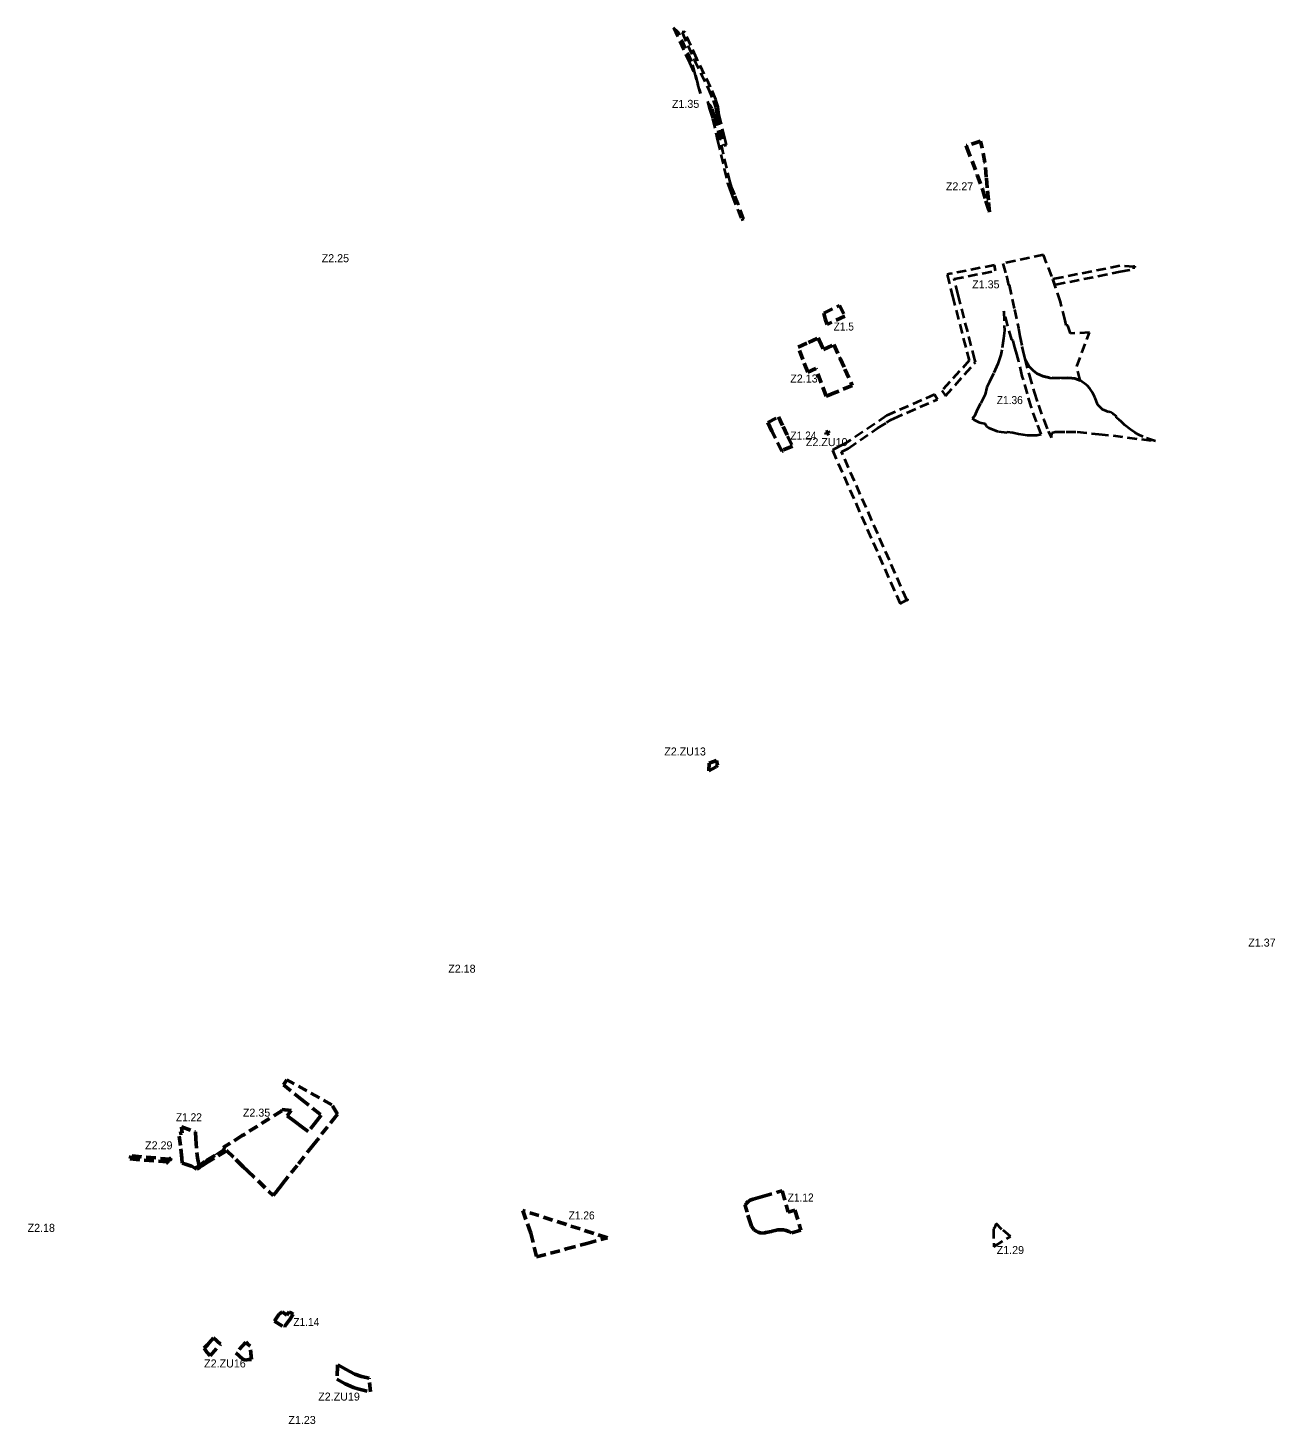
# Model space of a CAD drawing. Extents: x -650368 to -643203, y -1074215 to -1066658.
# Drawn here: x -650368 to -647095, y -1070321 to -1066658 of the extents above; entities that cross this region are included whole.
import ezdxf
from ezdxf.enums import TextEntityAlignment as Align

# ---------------------------------------------------------------- set-up
doc = ezdxf.new("R2010")
doc.units = 0
doc.header["$LTSCALE"] = 8.4
doc.header["$PDMODE"] = 32
doc.header["$PDSIZE"] = 4.2
doc.linetypes.add('MEDIUM_DASHED', pattern=[4.5, 3, -1.5])
for name, color, linetype, lineweight in [('1', 7, 'Continuous', 13), ('57', 7, 'MEDIUM_DASHED', 40), ('58', 7, 'MEDIUM_DASHED', 53)]:
    doc.layers.add(name, color=color, linetype=linetype, lineweight=lineweight)
for name, color, linetype in [('60', 7, 'Continuous'), ('61', 7, 'Continuous'), ('62', 7, 'Continuous')]:
    doc.layers.add(name, color=color, linetype=linetype)

msp = doc.modelspace()

# ---------------------------------------------------------------- linework, layer by layer
at = {"layer": '1'}
msp.add_line((-649849.496, -1069598.673), (-649903.756, -1069631.653), dxfattribs=at)
at = {"layer": '57'}
for p, q in [((-648495.63, -1067161.363), (-648489.1, -1067158.84)), ((-647408.2, -1067742.37), (-647440.81, -1067731.38))]:
    msp.add_line(p, q, dxfattribs=at)
for points in [[(-648602.97, -1066830.11), (-648616.86, -1066779.79), (-648625.44, -1066746.45), (-648659.95, -1066670.89), (-648662.46, -1066668.53), (-648673.407, -1066658.275), (-648631.791, -1066749.394)], [(-648576.145, -1066813.802), (-648612.763, -1066739.165), (-648643.925, -1066668.483), (-648651.042, -1066669.551), (-648651.1, -1066669.56)], [(-648651.1, -1066669.56), (-648619.11, -1066742.12), (-648582.52, -1066816.7)], [(-648631.791, -1066749.394), (-648616.104, -1066782.727), (-648602.97, -1066830.11)], [(-648582.52, -1066816.7), (-648569.13, -1066848.61), (-648566.63, -1066856.72), (-648563.48, -1066866.96), (-648560.2, -1066888.58), (-648541.521, -1066966.657), (-648534.701, -1066965.077), (-648538.812, -1066947.891)], [(-648538.812, -1066947.891), (-648553.323, -1066887.238), (-648556.637, -1066865.397), (-648559.94, -1066854.66), (-648562.542, -1066846.219), (-648576.145, -1066813.802)], [(-648571.96, -1066869.37), (-648577.99, -1066860.17), (-648583.94, -1066851.11), (-648578.702, -1066871.259)], [(-648578.702, -1066871.259), (-648571.167, -1066896.326), (-648557.816, -1066953.444)], [(-648489.1, -1067158.84), (-648512.95, -1067095.97), (-648520.4, -1067077.42), (-648524.93, -1067063.35), (-648533.66, -1067026), (-648551, -1066951.85), (-648564.4, -1066894.52), (-648571.96, -1066869.37)], [(-648557.816, -1066953.444), (-648540.476, -1067027.594), (-648531.681, -1067065.222)], [(-648531.681, -1067065.222), (-648526.988, -1067079.8), (-648519.471, -1067098.516), (-648495.644, -1067161.326)], [(-647638.68, -1067439.06), (-647642.686, -1067438.46), (-647645.78, -1067425.81), (-647658.13, -1067376.99), (-647680.64, -1067310.37), (-647702.42, -1067253.98), (-647809.02, -1067276.271)], [(-647809.02, -1067276.271), (-647799.76, -1067308.3), (-647794.54, -1067333.14)], [(-647948.488, -1067303.671), (-647955.805, -1067305.106), (-647941.289, -1067362.104)], [(-647882.66, -1067529.231), (-647926.759, -1067358.379), (-647937.355, -1067316.774), (-647828.376, -1067295.406), (-647828.104, -1067295.352), (-647831.28, -1067280.69), (-647948.488, -1067303.671)], [(-647465.203, -1067285.115), (-647501.968, -1067282.642), (-647673.685, -1067316.666), (-647678.21, -1067317.562), (-647673.367, -1067331.895), (-647670.77, -1067331.38), (-647501.099, -1067297.762)], [(-647501.099, -1067297.762), (-647465.699, -1067290.747), (-647465.203, -1067285.115)], [(-647794.54, -1067333.14), (-647792.52, -1067332.74), (-647778.78, -1067397.1), (-647768.5, -1067446.04), (-647764.89, -1067466.64), (-647759.16, -1067494.01)], [(-647941.289, -1067362.104), (-647897.637, -1067531.223), (-647969.29, -1067609.79), (-647959.832, -1067623.65)], [(-647773.96, -1067508.48), (-647777.55, -1067496.95), (-647781.85, -1067479.19), (-647785.64, -1067477.02), (-647806.8, -1067401.51), (-647804.88, -1067452.07), (-647807.17, -1067473.06), (-647811.8, -1067502.42), (-647814.89, -1067515.91), (-647822.82, -1067539.89), (-647833.51, -1067565.03), (-647844.04, -1067587.17)], [(-647751.41, -1067526.58), (-647740.124, -1067546.265), (-647729.802, -1067557.462), (-647719.661, -1067564.884), (-647704.458, -1067572.034), (-647685.968, -1067576.68), (-647654.743, -1067576.996), (-647640.087, -1067576.306), (-647628.441, -1067576.759), (-647620.586, -1067578.478), (-647606.559, -1067583.309), (-647614.75, -1067546.53), (-647582.2, -1067457.65), (-647631.59, -1067459.72), (-647638.68, -1067439.06)], [(-647759.16, -1067494.01), (-647756.55, -1067505.32), (-647751.41, -1067526.58)], [(-647959.832, -1067623.65), (-647881.085, -1067535.333), (-647882.66, -1067529.231)], [(-647708.71, -1067723.99), (-647721.05, -1067691.73), (-647734.63, -1067652.57), (-647744.61, -1067617.96), (-647758.25, -1067571.79), (-647768.5, -1067529.75), (-647773.96, -1067508.48)], [(-647547.663, -1067659.519), (-647560.187, -1067647.458), (-647567.744, -1067627.24), (-647573.605, -1067614.951), (-647580.539, -1067604.432), (-647586.864, -1067597.411), (-647591.227, -1067593.613), (-647604.415, -1067584.047), (-647620.586, -1067578.478), (-647628.441, -1067576.759), (-647640.087, -1067576.306), (-647654.743, -1067576.996), (-647685.968, -1067576.68), (-647704.458, -1067572.034), (-647719.661, -1067564.884), (-647729.802, -1067557.462), (-647740.124, -1067546.265), (-647751.41, -1067526.58)], [(-647751.41, -1067526.58), (-647740.49, -1067568.67), (-647727.37, -1067614.33), (-647715.92, -1067648.12), (-647702.04, -1067686.86), (-647690.09, -1067716.05), (-647681.91, -1067732.74)], [(-647844.04, -1067587.17), (-647850.96, -1067600.4), (-647855.65, -1067620.33), (-647867.53, -1067643.84)], [(-647988.235, -1067619.912), (-648114.145, -1067675.531), (-648222.872, -1067748.412), (-648238.748, -1067756.759), (-648256.499, -1067766.091), (-648079.002, -1068168.139), (-648061.329, -1068158.649)], [(-648215.115, -1067761.28), (-648137.869, -1067708.325), (-648114.323, -1067693.403), (-648103.383, -1067686.47), (-648103.298, -1067686.416), (-648095.475, -1067682.994), (-647983.403, -1067633.963), (-647983.06, -1067633.813), (-647980.561, -1067632.719), (-647982.95, -1067628.73), (-647988.235, -1067619.912)], [(-647867.53, -1067643.84), (-647876.15, -1067658.82), (-647883.78, -1067676.59), (-647886.95, -1067680.13), (-647889.94, -1067681.81)], [(-647889.94, -1067681.81), (-647884.25, -1067686.21), (-647882.82, -1067687.32), (-647871.87, -1067692.85), (-647869.32, -1067693.61), (-647865.76, -1067694.68), (-647856.9, -1067695.97)], [(-647499.095, -1067691.163), (-647503.97, -1067686.73), (-647510.6, -1067680.86), (-647511.24, -1067677.53), (-647517.74, -1067672.85), (-647520.13, -1067671.13), (-647527.76, -1067665.65), (-647530.82, -1067666.65), (-647536.83, -1067663.64), (-647547.663, -1067659.519)], [(-647856.9, -1067695.97), (-647852.3, -1067703.36), (-647845.74, -1067707.59), (-647821.02, -1067717.33), (-647798.5, -1067719.67), (-647798.17, -1067717.58), (-647783.13, -1067719.68), (-647768.53, -1067722.82), (-647745.41, -1067726.6), (-647732.71, -1067727.02), (-647720.45, -1067726.49), (-647708.71, -1067723.99)], [(-647681.91, -1067732.74), (-647680.804, -1067720.745), (-647672, -1067718), (-647643, -1067718), (-647614, -1067718), (-647557, -1067724), (-647520.145, -1067727.879), (-647408.2, -1067742.37)], [(-647440.81, -1067731.38), (-647453.87, -1067724.97), (-647462.45, -1067719.84), (-647474.13, -1067711.81), (-647489.3, -1067700.07), (-647499.095, -1067691.163)], [(-648061.329, -1068158.649), (-648232.676, -1067770.513), (-648215.115, -1067761.28)]]:
    msp.add_lwpolyline(points, dxfattribs=at)
at = {"layer": '57', "lineweight": 53}
for points in [[(-648279.24, -1067406.38), (-648237.881, -1067386.158), (-648237.873, -1067386.174), (-648237.865, -1067386.17), (-648224.19, -1067414.14), (-648270.02, -1067436.37), (-648275.41, -1067421.3)], [(-648397.98, -1067678.79), (-648385.86, -1067704.19), (-648373.99, -1067728.95), (-648361.08, -1067755.88), (-648387.04, -1067765.67), (-648386.12, -1067767.45), (-648389.29, -1067768.64), (-648415.164, -1067716.136), (-648426.366, -1067693.402)], [(-649967.81, -1069590.74), (-649971.38, -1069558.79), (-649963.43, -1069557.91), (-649965.26, -1069541.51), (-649928.48, -1069554.57), (-649927.304, -1069572.44), (-649924.62, -1069608.53), (-649923.17, -1069623.14), (-649918.354, -1069643.452), (-649917.38, -1069647.56), (-649924.8, -1069652.19), (-649928.67, -1069649.89), (-649938.2, -1069644.23), (-649954.38, -1069639.1), (-649962.71, -1069636.46), (-649964.11, -1069623.91)], [(-648339.05, -1069812.45), (-648363.68, -1069819.31), (-648371.21, -1069815.56), (-648378.1, -1069813.29), (-648385.21, -1069811.91), (-648392.45, -1069811.44), (-648399.68, -1069811.88), (-648406.84, -1069813.23), (-648414.657, -1069815.246), (-648415.99, -1069815.59), (-648430.881, -1069818.663), (-648433.97, -1069819.3), (-648439.89, -1069819.97), (-648445.8, -1069819.51), (-648451.53, -1069817.98), (-648456.88, -1069815.39), (-648461.64, -1069811.86), (-648465.67, -1069807.49), (-648468.82, -1069802.44), (-648470.97, -1069796.9), (-648480.267, -1069765.316), (-648485.44, -1069747.39), (-648485.14, -1069746.55), (-648483.274, -1069743.777), (-648481.79, -1069741.57), (-648477.39, -1069737.44), (-648476.022, -1069736.525), (-648472.4, -1069734.1), (-648464.45, -1069730.89), (-648439.8, -1069724.19), (-648401.288, -1069713.154), (-648388.631, -1069709.738), (-648372.639, -1069765.241), (-648355.015, -1069760.287)], [(-649069.4, -1069760.67), (-649048, -1069820), (-649032.928, -1069882.782), (-648955.211, -1069861.806), (-648901.185, -1069847.225), (-648846.924, -1069832.58)], [(-649676.46, -1070039.89), (-649671.82, -1070033.15), (-649678.92, -1070028.51), (-649682.07, -1070026.45), (-649686.55, -1070033.29), (-649688.24, -1070035.47), (-649692, -1070033.14), (-649691.64, -1070032.56), (-649700.69, -1070026.36), (-649709.67, -1070034.09), (-649718.51, -1070046.94), (-649721.11, -1070051.18), (-649694.06, -1070067.08), (-649693.23, -1070065.13), (-649691.7, -1070062.02), (-649685.84, -1070053.65), (-649679.2, -1070044.17)]]:
    msp.add_lwpolyline(points, close=True, dxfattribs=at)
at = {"layer": '57'}
msp.add_lwpolyline([(-647833.172, -1069855.944), (-647833.172, -1069855.944), (-647831.62, -1069854.99), (-647789.55, -1069829.12), (-647811.83, -1069810.39), (-647827.16, -1069795.32), (-647831.32, -1069806.56), (-647833.91, -1069808.91), (-647833.2, -1069854.15)], close=True, dxfattribs=at)
for p in [(-647465.203, -1067285.115), (-648061.329, -1068158.649)]:
    msp.add_point(p, dxfattribs=at)
at = {"layer": '58'}
for points in [[(-647903.5, -1066972.05), (-647876.57, -1067043.5), (-647863.04, -1067081.36), (-647853.65, -1067111.91), (-647844.3, -1067141.25), (-647847.09, -1067110.58), (-647850.07, -1067077.71), (-647852.63, -1067049.52), (-647856.11, -1067011.21), (-647866.14, -1066961.98), (-647867.46, -1066955.52), (-647905.28, -1066967.07)], [(-648254.04, -1067616.96), (-648265.601, -1067621.762), (-648272.941, -1067624.811), (-648299.23, -1067554.52), (-648300.258, -1067551.772), (-648321.36, -1067561.69), (-648334.09, -1067528.2), (-648346.27, -1067496.14), (-648319.7, -1067483.53), (-648319.7, -1067483.53), (-648294.04, -1067471.35), (-648291.17, -1067477.57), (-648279.86, -1067502.11), (-648253.1, -1067489.23), (-648237.81, -1067522.42), (-648236.51, -1067525.24), (-648223.55, -1067553.354), (-648204.88, -1067596.54)], [(-648267.25, -1067716.9), (-648273.97, -1067719.29), (-648272.02, -1067724.45), (-648269.15, -1067723.37), (-648264.95, -1067721.79)], [(-648579.97, -1068587.39), (-648580.66, -1068607.64), (-648561.49, -1068596.84), (-648558.08, -1068592.36), (-648560.79, -1068580.12)], [(-650002.39, -1069633.65), (-649994.913, -1069626.246), (-650096.627, -1069617.746), (-650099.55, -1069625.53), (-650062.45, -1069628.63)], [(-649897.03, -1070113.07), (-649905.51, -1070122.35), (-649898.55, -1070132.9), (-649889.87, -1070141.83), (-649862.22, -1070111.54), (-649880.42, -1070094.87), (-649886.83, -1070101.89)], [(-649784.87, -1070116.76), (-649791.58, -1070110.83), (-649796.4, -1070106.56), (-649821.97, -1070134.58), (-649804.29, -1070150.68), (-649797.33, -1070153.41), (-649787.92, -1070152.23), (-649781.432, -1070151.628)], [(-649557.21, -1070203.53), (-649535, -1070216), (-649513, -1070225), (-649502.36, -1070228.94), (-649469.02, -1070236.92), (-649472.43, -1070202.9), (-649472.6, -1070201.15), (-649492.67, -1070196.34), (-649509.72, -1070190.24), (-649523.21, -1070183.06), (-649532.57, -1070178.08), (-649555.44, -1070165.91), (-649555.15, -1070169.51)]]:
    msp.add_lwpolyline(points, close=True, dxfattribs=at)
for points in [[(-649688.625, -1069418.156), (-649697.525, -1069431.522), (-649650.425, -1069468.85), (-649619.983, -1069493.184), (-649598.004, -1069510.814), (-649610.429, -1069526.497), (-649632.179, -1069553.95), (-649649.31, -1069541.16), (-649667.74, -1069527.4), (-649687.77, -1069512.44), (-649677.02, -1069498.32), (-649701.7, -1069495.89), (-649701.57, -1069499.21), (-649801.49, -1069561.98), (-649805.22, -1069564.32), (-649855.34, -1069595.8), (-649850.24, -1069600.295), (-649877.129, -1069617.006), (-649903.292, -1069632.541), (-649918.35, -1069643.45), (-649928.67, -1069649.89), (-649924.8, -1069652.19), (-649920.45, -1069649.53), (-649917.38, -1069647.56), (-649907.07, -1069640.92), (-649900.64, -1069636.78), (-649846.38, -1069603.8), (-649822.26, -1069627.2), (-649818.71, -1069630.64), (-649802.9, -1069645.96), (-649791.3, -1069657.21)], [(-649561.17, -1069515.83), (-649558.71, -1069512.62), (-649555.16, -1069508.07), (-649570.03, -1069483.83), (-649688.625, -1069418.156)], [(-649620.45, -1069590.75), (-649574.1, -1069531.97), (-649571.94, -1069529.24), (-649561.17, -1069515.83)], [(-649724.51, -1069721.57), (-649714.03, -1069709.09), (-649712.64, -1069707.43), (-649705.28, -1069698.11), (-649700.42, -1069691.8), (-649658.13, -1069638.84), (-649620.45, -1069590.75)], [(-649791.3, -1069657.21), (-649763.31, -1069683.5), (-649763.31, -1069683.5), (-649724.51, -1069721.57)]]:
    msp.add_lwpolyline(points, dxfattribs=at)
for p in [(-650002.39, -1069633.65), (-649994.913, -1069626.246)]:
    msp.add_point(p, dxfattribs=at)

# ---------------------------------------------------------------- texts
at = {"layer": '60'}
for s, p in [('Z1.35', (-648641.847, -1066868.029)), ('Z1.35', (-647853.88, -1067341.475)), ('Z1.37', (-647129.255, -1069068.508)), ('Z1.29', (-647789.527, -1069875.149)), ('Z1.23', (-649648.392, -1070320.945))]:
    msp.add_text(s, height=21, dxfattribs=at).set_placement(p, align=Align.CENTER)
at = {"layer": '60', "width": 0.95}
for s, p in [('Z1.5', (-648226.743, -1067452.194)), ('Z1.36', (-647790.96, -1067645.188)), ('Z1.24', (-648332.556, -1067738.122)), ('Z1.22', (-649945.368, -1069526.711)), ('Z1.12', (-648339.89, -1069737.306)), ('Z1.26', (-648914.702, -1069784.313)), ('Z1.14', (-649637.253, -1070063.973))]:
    msp.add_text(s, height=21, dxfattribs=at).set_placement(p, align=Align.CENTER)
at = {"layer": '61'}
for s, p in [('Z2.27', (-647922.882, -1067084.411)), ('Z2.13', (-648331.178, -1067588.562)), ('Z2.ZU10', (-648271.539, -1067755.404)), ('Z2.ZU13', (-648643.248, -1068567.089)), ('Z2.35', (-649767.849, -1069514.654)), ('Z2.29', (-650024.478, -1069600.414)), ('Z2.ZU16', (-649850.907, -1070172.691)), ('Z2.ZU19', (-649551.432, -1070259.616))]:
    msp.add_text(s, height=21, dxfattribs=at).set_placement(p, align=Align.CENTER)
at = {"layer": '62'}
for s, p in [('Z2.25', (-649561.009, -1067272.925)), ('Z2.18', (-649228.931, -1069136.994)), ('Z2.18', (-650332.906, -1069816.873))]:
    msp.add_text(s, height=21, dxfattribs=at).set_placement(p, align=Align.CENTER)

doc.saveas('drawing.dxf')
